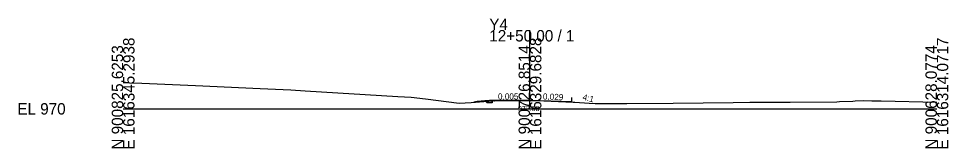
# Model space of a CAD drawing. Extents: x -26 to 2603, y -10 to 522.
# Drawn here: x -25.7 to 202.8, y 490.3 to 522.1 of the extents above; entities that cross this region are included whole.
import ezdxf

# ---------------------------------------------------------------- set-up
doc = ezdxf.new("R2010")
doc.units = 0
for name, color, linetype in [('Exist Cross Section Cell', 7, 'Continuous'), ('Exist XS Center Line Elevation Label', 7, 'Continuous'), ('Exist XS Ground Line', 7, 'Continuous'), ('Prop XS Ditch Slope Text', 7, 'Continuous'), ('Prop XS Dump Level', 7, 'Continuous'), ('Prop XS Earthwork Shape', 7, 'Continuous'), ('Prop XS EOT Tick Mark', 7, 'Continuous'), ('Prop XS Finish Grade', 7, 'Continuous'), ('Prop XS Finish Grade Earthwork', 7, 'Continuous'), ('Prop XS Finish Grade Pavement', 7, 'Continuous'), ('Prop XS Pvmt Edge Slope', 7, 'Continuous'), ('Prop XS SE Text', 7, 'Continuous'), ('Prop XS Subgrade Earthwork', 7, 'Continuous')]:
    doc.layers.add(name, color=color, linetype=linetype)

msp = doc.modelspace()

# ---------------------------------------------------------------- linework, layer by layer
at = {"layer": 'Exist Cross Section Cell'}
for p, q in [((100, 500), (100, 519.33)), ((0, 500), (100, 500)), ((100, 500), (200, 500))]:
    msp.add_line(p, q, dxfattribs=at)
at = {"layer": 'Exist XS Ground Line'}
for p, q in [((0, 506.44), (1.58, 506.39)), ((0, 506.44), (1.58, 506.39)), ((1.58, 506.39), (4.62, 506.26)), ((1.58, 506.39), (4.62, 506.26)), ((4.62, 506.26), (10.28, 506.06)), ((4.62, 506.26), (10.28, 506.06)), ((10.28, 506.06), (17.76, 505.74)), ((10.28, 506.06), (17.76, 505.74)), ((17.76, 505.74), (33.7, 504.96)), ((17.76, 505.74), (33.7, 504.96)), ((33.7, 504.96), (41.24, 504.67)), ((33.7, 504.96), (41.24, 504.67)), ((41.24, 504.67), (44.74, 504.45)), ((41.24, 504.67), (44.74, 504.45)), ((44.74, 504.45), (67.54, 503.02)), ((44.74, 504.45), (67.54, 503.02)), ((67.54, 503.02), (70.78, 502.87)), ((67.54, 503.02), (70.78, 502.87)), ((70.78, 502.87), (74.34, 502.45)), ((70.78, 502.87), (74.34, 502.45)), ((74.34, 502.45), (82.62, 501.37)), ((74.34, 502.45), (82.62, 501.37)), ((82.62, 501.37), (85.53, 501.55)), ((82.62, 501.37), (85.53, 501.55)), ((85.53, 501.55), (90.69, 501.98)), ((85.53, 501.55), (90.69, 501.98)), ((90.69, 501.98), (97.07, 502.04)), ((90.69, 501.98), (97.07, 502.04)), ((97.07, 502.04), (100.26, 502.08)), ((97.07, 502.04), (100.26, 502.08)), ((100.26, 502.08), (103.42, 501.96)), ((100.26, 502.08), (103.42, 501.96)), ((103.42, 501.96), (110.62, 501.67)), ((103.42, 501.96), (110.62, 501.67)), ((110.62, 501.67), (111, 501.63)), ((110.62, 501.67), (111, 501.63)), ((111, 501.63), (114.56, 501.36)), ((111, 501.63), (114.56, 501.36)), ((114.56, 501.36), (116.03, 501.3)), ((114.56, 501.36), (116.03, 501.3)), ((116.03, 501.3), (122.26, 501.31)), ((116.03, 501.3), (122.26, 501.31)), ((122.26, 501.31), (123.78, 501.32)), ((122.26, 501.31), (123.78, 501.32)), ((123.78, 501.32), (135.21, 501.41)), ((123.78, 501.32), (135.21, 501.41)), ((135.21, 501.41), (149.95, 501.57)), ((135.21, 501.41), (149.95, 501.57)), ((149.95, 501.57), (154, 501.6)), ((149.95, 501.57), (154, 501.6)), ((154, 501.6), (163.98, 501.67)), ((154, 501.6), (163.98, 501.67)), ((163.98, 501.67), (175.41, 501.76)), ((163.98, 501.67), (175.41, 501.76)), ((175.41, 501.76), (176.07, 501.82)), ((175.41, 501.76), (176.07, 501.82)), ((176.07, 501.82), (179.33, 501.9)), ((176.07, 501.82), (179.33, 501.9)), ((179.33, 501.9), (179.94, 502)), ((179.33, 501.9), (179.94, 502)), ((179.94, 502), (181.89, 502.01)), ((179.94, 502), (181.89, 502.01)), ((181.89, 502.01), (184.05, 501.96)), ((181.89, 502.01), (184.05, 501.96)), ((184.05, 501.96), (186.33, 501.94)), ((184.05, 501.96), (186.33, 501.94)), ((186.33, 501.94), (200, 501.61)), ((186.33, 501.94), (200, 501.61))]:
    msp.add_line(p, q, dxfattribs=at)
at = {"layer": 'Prop XS Earthwork Shape'}
for points in [[(86.23, 501.6), (89.06, 501.85), (88.94, 501.96), (87.05, 501.81)], [(89.06, 501.85), (89.92, 501.92), (89.45, 501.45)], [(89.92, 501.92), (90.69, 501.98), (90.69, 501.48), (89.45, 501.45)]]:
    msp.add_lwpolyline(points, close=True, dxfattribs=at)
at = {"layer": 'Prop XS EOT Tick Mark'}
msp.add_line((110.28, 501.77), (110.28, 502.77), dxfattribs=at)
at = {"layer": 'Prop XS Finish Grade'}
msp.add_line((90.05, 502.05), (88.94, 501.96), dxfattribs=at)
at = {"layer": 'Prop XS Finish Grade Earthwork'}
for p, q in [((87.05, 501.81), (86.23, 501.6)), ((88.94, 501.96), (87.05, 501.81))]:
    msp.add_line(p, q, dxfattribs=at)
at = {"layer": 'Prop XS Finish Grade Pavement'}
for q in [(90.05, 502.05), (110.28, 501.77)]:
    msp.add_line((100, 502.1), q, dxfattribs=at)
at = {"layer": 'Prop XS Pvmt Edge Slope'}
msp.add_line((90.05, 502.05), (89.45, 501.45), dxfattribs=at)
at = {"layer": 'Prop XS Subgrade Earthwork'}
for p, q in [((89.45, 501.45), (88.94, 501.96)), ((90.69, 501.48), (89.45, 501.45)), ((90.05, 501.47), (90.05, 501.47)), ((90.69, 501.48), (90.69, 501.98))]:
    msp.add_line(p, q, dxfattribs=at)

# ---------------------------------------------------------------- texts
at = {"layer": 'Exist Cross Section Cell'}
for s, p in [('Y4', (90, 519.33)), ('12+50.00 / 1', (90, 516.53)), ('EL 970', (-26, 498.6))]:
    msp.add_text(s, height=2.8, dxfattribs=at).set_placement(p)
for s, p in [('E 1616345.2938', (2.8, 490)), ('E 1616329.6828', (102.8, 490)), ('E 1616314.0717', (202.8, 490)), ('N 900825.6253', (0, 490)), ('N 900726.8514', (100, 490)), ('N 900628.0774', (200, 490))]:
    msp.add_text(s, height=2.8, rotation=90, dxfattribs=at).set_placement(p)
at = {"layer": 'Exist XS Center Line Elevation Label'}
msp.add_text('972.08', height=1.25, dxfattribs=at).set_placement((97.05, 499.45))
at = {"layer": 'Prop XS Ditch Slope Text'}
msp.add_text('4:1', height=1.5, rotation=345.9638, dxfattribs=at).set_placement((112.82, 502.24))
at = {"layer": 'Prop XS Dump Level'}
msp.add_text('Eop', height=0.3, rotation=360, dxfattribs=at).set_placement((90.69, 501.68))
at = {"layer": 'Prop XS SE Text'}
for s, rotation, p in [('0.005', 359.9916, (92.14, 502.29)), ('0.029', 357.7874, (103.15, 502.3))]:
    msp.add_text(s, height=1.5, rotation=rotation, dxfattribs=at).set_placement(p)

doc.saveas('drawing.dxf')
